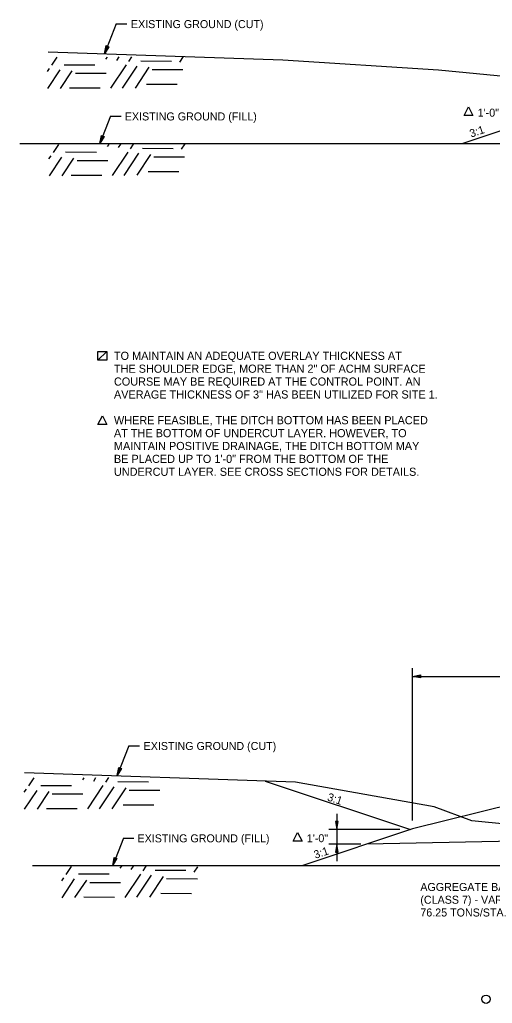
# Model space of a CAD drawing. Extents: x 1398565 to 1398920, y 1968324 to 1968581.
# Drawn here: x 1398564.8 to 1398599.7, y 1968486.6 to 1968559.1 of the extents above; entities that cross this region are included whole.
import ezdxf

# ---------------------------------------------------------------- set-up
doc = ezdxf.new("R2010")
doc.units = 0
for name, color, linetype in [('10', 7, 'Continuous'), ('19', 7, 'Continuous'), ('42', 7, 'Continuous'), ('9', 7, 'Continuous'), ('Default', 7, 'Continuous')]:
    doc.layers.add(name, color=color, linetype=linetype)

msp = doc.modelspace()

# ---------------------------------------------------------------- linework, layer by layer
at = {"layer": '10'}
for points in [[(1398597.924, 1968552.659), (1398598.245, 1968552.018), (1398597.604, 1968552.018)], [(1398570.61, 1968534.616), (1398571.251, 1968534.616), (1398571.251, 1968533.975), (1398570.61, 1968533.975)], [(1398570.61, 1968534.616), (1398571.251, 1968534.616), (1398570.61, 1968533.975)], [(1398570.93, 1968529.866), (1398571.251, 1968529.225), (1398570.61, 1968529.225)], [(1398585.328, 1968499.163), (1398585.649, 1968498.522), (1398585.008, 1968498.522)]]:
    msp.add_lwpolyline(points, close=True, dxfattribs=at)
msp.add_circle((1398599.214, 1968486.865), 0.306, dxfattribs=at)
at = {"layer": '19'}
for p, q in [((1398571.954, 1968558.774), (1398571.097, 1968556.572)), ((1398571.954, 1968558.774), (1398572.736, 1968558.774)), ((1398571.097, 1968556.572), (1398571.217, 1968557.17)), ((1398571.413, 1968557.093), (1398571.097, 1968556.572)), ((1398571.141, 1968556.727), (1398571.268, 1968557.15)), ((1398571.366, 1968557.112), (1398571.169, 1968556.716)), ((1398571.217, 1968557.17), (1398571.413, 1968557.093)), ((1398604.859, 1968552.402), (1398597.492, 1968549.946)), ((1398571.543, 1968551.966), (1398570.757, 1968549.946)), ((1398571.543, 1968551.966), (1398572.325, 1968551.966)), ((1398570.757, 1968549.946), (1398570.877, 1968550.543)), ((1398571.073, 1968550.467), (1398570.757, 1968549.946)), ((1398570.801, 1968550.1), (1398570.928, 1968550.523)), ((1398571.026, 1968550.485), (1398570.829, 1968550.09)), ((1398570.877, 1968550.543), (1398571.073, 1968550.467)), ((1398593.795, 1968500.033), (1398593.795, 1968511.264)), ((1398593.795, 1968510.664), (1398594.395, 1968510.769)), ((1398593.795, 1968510.664), (1398617.795, 1968510.664)), ((1398594.395, 1968510.559), (1398593.795, 1968510.664)), ((1398593.955, 1968510.679), (1398594.395, 1968510.714)), ((1398594.395, 1968510.609), (1398593.955, 1968510.649)), ((1398594.395, 1968510.769), (1398594.395, 1968510.559)), ((1398572.889, 1968505.548), (1398572.033, 1968503.347)), ((1398572.889, 1968505.548), (1398573.672, 1968505.548)), ((1398572.033, 1968503.347), (1398572.153, 1968503.944)), ((1398572.348, 1968503.868), (1398572.033, 1968503.347)), ((1398572.077, 1968503.501), (1398572.204, 1968503.924)), ((1398572.302, 1968503.886), (1398572.105, 1968503.491)), ((1398572.153, 1968503.944), (1398572.348, 1968503.868)), ((1398582.932, 1968502.938), (1398593.647, 1968499.367)), ((1398609.795, 1968503.416), (1398593.795, 1968499.416)), ((1398588.217, 1968500.525), (1398588.217, 1968499.249)), ((1398593.795, 1968499.416), (1398585.707, 1968496.72)), ((1398588.322, 1968499.967), (1398588.112, 1968499.967)), ((1398588.112, 1968499.967), (1398588.217, 1968499.367)), ((1398588.167, 1968499.967), (1398588.202, 1968499.527)), ((1398588.217, 1968499.367), (1398588.322, 1968499.967)), ((1398588.217, 1968499.249), (1398588.217, 1968497.043)), ((1398588.232, 1968499.527), (1398588.272, 1968499.967)), ((1398642.795, 1968499.341), (1398590.426, 1968498.293)), ((1398572.479, 1968498.74), (1398571.693, 1968496.72)), ((1398572.479, 1968498.74), (1398573.261, 1968498.74)), ((1398588.217, 1968498.293), (1398588.112, 1968497.693)), ((1398588.202, 1968498.133), (1398588.167, 1968497.693)), ((1398588.322, 1968497.693), (1398588.217, 1968498.293)), ((1398588.272, 1968497.693), (1398588.232, 1968498.133)), ((1398571.693, 1968496.72), (1398571.812, 1968497.318)), ((1398572.008, 1968497.242), (1398571.693, 1968496.72)), ((1398571.737, 1968496.875), (1398571.864, 1968497.298)), ((1398571.962, 1968497.26), (1398571.765, 1968496.864)), ((1398571.812, 1968497.318), (1398572.008, 1968497.242)), ((1398588.112, 1968497.693), (1398588.322, 1968497.693))]:
    msp.add_line(p, q, dxfattribs=at)
at = {"layer": '42'}
for points in [[(1398613.903, 1968550.586), (1398606.201, 1968553.623), (1398601.314, 1968554.831), (1398595.7, 1968555.373), (1398584.241, 1968556.087), (1398566.939, 1968556.681)], [(1398564.837, 1968549.946), (1398611.333, 1968549.946), (1398635.859, 1968556.055), (1398641.859, 1968556.295)], [(1398564.837, 1968549.946), (1398610.787, 1968549.946)], [(1398612.268, 1968496.72), (1398600.898, 1968499.734), (1398598.177, 1968500.018), (1398595.382, 1968501.049), (1398585.177, 1968502.861), (1398565.203, 1968503.547)], [(1398565.772, 1968496.72), (1398612.268, 1968496.72), (1398636.795, 1968502.83), (1398642.795, 1968503.07)], [(1398565.772, 1968496.72), (1398612.268, 1968496.72), (1398636.795, 1968502.83), (1398642.795, 1968503.07)]]:
    msp.add_lwpolyline(points, dxfattribs=at)
at = {"layer": '9'}
for p, q in [((1398567.214, 1968555.725), (1398567.602, 1968556.308)), ((1398571.198, 1968556.174), (1398571.301, 1968556.328)), ((1398571.995, 1968556.085), (1398572.16, 1968556.333)), ((1398572.886, 1968555.998), (1398573.113, 1968556.338)), ((1398573.775, 1968556.04), (1398576.037, 1968556.034)), ((1398576.65, 1968555.963), (1398576.914, 1968556.36)), ((1398566.876, 1968555.252), (1398567.03, 1968555.483)), ((1398566.904, 1968554.009), (1398567.828, 1968555.394)), ((1398567.857, 1968554.015), (1398568.718, 1968555.307)), ((1398568.104, 1968555.767), (1398570.366, 1968555.761)), ((1398568.941, 1968555.141), (1398571.203, 1968555.135)), ((1398571.555, 1968554.035), (1398572.702, 1968555.756)), ((1398572.415, 1968554.04), (1398573.5, 1968555.667)), ((1398573.367, 1968554.045), (1398574.39, 1968555.58)), ((1398574.613, 1968555.414), (1398576.875, 1968555.408)), ((1398568.502, 1968554.063), (1398570.764, 1968554.057)), ((1398574.174, 1968554.336), (1398576.436, 1968554.33)), ((1398567.336, 1968549.289), (1398567.724, 1968549.872)), ((1398568.226, 1968549.331), (1398570.488, 1968549.325)), ((1398571.32, 1968549.738), (1398571.422, 1968549.892)), ((1398571.677, 1968547.6), (1398572.824, 1968549.32)), ((1398572.117, 1968549.65), (1398572.282, 1968549.897)), ((1398573.008, 1968549.562), (1398573.235, 1968549.903)), ((1398573.897, 1968549.604), (1398576.159, 1968549.598)), ((1398576.772, 1968549.527), (1398577.036, 1968549.924)), ((1398566.998, 1968548.816), (1398567.152, 1968549.047)), ((1398567.026, 1968547.574), (1398567.95, 1968548.959)), ((1398567.979, 1968547.579), (1398568.84, 1968548.871)), ((1398569.063, 1968548.705), (1398571.325, 1968548.699)), ((1398572.537, 1968547.604), (1398573.622, 1968549.232)), ((1398573.489, 1968547.61), (1398574.512, 1968549.144)), ((1398574.735, 1968548.978), (1398576.997, 1968548.972)), ((1398574.296, 1968547.9), (1398576.558, 1968547.894)), ((1398568.624, 1968547.627), (1398570.886, 1968547.621)), ((1398565.513, 1968502.59), (1398565.901, 1968503.173)), ((1398569.497, 1968503.039), (1398569.6, 1968503.193)), ((1398570.294, 1968502.95), (1398570.46, 1968503.198)), ((1398571.185, 1968502.863), (1398571.412, 1968503.203)), ((1398572.075, 1968502.905), (1398574.337, 1968502.899)), ((1398565.175, 1968502.117), (1398565.329, 1968502.348)), ((1398565.203, 1968500.874), (1398566.127, 1968502.259)), ((1398566.156, 1968500.88), (1398567.017, 1968502.172)), ((1398566.403, 1968502.632), (1398568.665, 1968502.626)), ((1398569.854, 1968500.9), (1398571.001, 1968502.621)), ((1398570.714, 1968500.905), (1398571.799, 1968502.532)), ((1398571.666, 1968500.91), (1398572.689, 1968502.445)), ((1398572.912, 1968502.279), (1398575.174, 1968502.273)), ((1398567.241, 1968502.006), (1398569.502, 1968502)), ((1398566.802, 1968500.928), (1398569.064, 1968500.922)), ((1398572.473, 1968501.201), (1398574.735, 1968501.195)), ((1398568.271, 1968496.064), (1398568.66, 1968496.646)), ((1398572.255, 1968496.513), (1398572.358, 1968496.667)), ((1398573.053, 1968496.424), (1398573.218, 1968496.672)), ((1398573.943, 1968496.336), (1398574.17, 1968496.677)), ((1398574.833, 1968496.379), (1398577.095, 1968496.373)), ((1398577.707, 1968496.219), (1398577.971, 1968496.615)), ((1398567.934, 1968495.591), (1398568.087, 1968495.822)), ((1398567.962, 1968494.348), (1398568.885, 1968495.733)), ((1398568.914, 1968494.353), (1398569.776, 1968495.645)), ((1398569.161, 1968496.106), (1398571.423, 1968496.1)), ((1398572.613, 1968494.374), (1398573.759, 1968496.094)), ((1398573.472, 1968494.379), (1398574.557, 1968496.006)), ((1398574.425, 1968494.384), (1398575.448, 1968495.918)), ((1398575.671, 1968495.753), (1398577.933, 1968495.747)), ((1398569.999, 1968495.48), (1398572.261, 1968495.474)), ((1398569.56, 1968494.402), (1398571.822, 1968494.396)), ((1398575.232, 1968494.674), (1398577.494, 1968494.669))]:
    msp.add_line(p, q, dxfattribs=at)
at = {"layer": 'Default'}
for p, q in [((1398592.871, 1968499.367), (1398587.622, 1968499.367)), ((1398589.989, 1968498.293), (1398587.637, 1968498.293))]:
    msp.add_line(p, q, dxfattribs=at)

# ---------------------------------------------------------------- texts
at = {"layer": '10'}
for s, height, rotation, p in [('EXISTING GROUND (CUT)', 0.59001, 360, (1398573.038, 1968558.463)), ('EXISTING GROUND (FILL)', 0.59001, 360, (1398572.585, 1968551.655)), ('1\'-0"', 0.59, 360, (1398598.599, 1968551.932)), ('3:1', 0.59, 18.49392, (1398598.115, 1968550.388)), ('EXISTING GROUND (CUT)', 0.59001, 360, (1398573.973, 1968505.238)), ('3:1', 0.59, 341.52236, (1398587.466, 1968501.529)), ('EXISTING GROUND (FILL)', 0.59001, 360, (1398573.52, 1968498.429)), ('1\'-0"', 0.59, 360, (1398586.002, 1968498.436)), ('3:1', 0.59, 18.49392, (1398586.63, 1968497.213))]:
    msp.add_text(s, height=height, rotation=rotation, dxfattribs=at).set_placement(p)
at = {"layer": '19'}
for s, p in [('AGGREGATE BASE COURSE', (1398594.371, 1968494.842)), ('(CLASS 7) - VAR. COMPACTED DEPTH', (1398594.371, 1968493.902)), ('76.25 TONS/STA.', (1398594.371, 1968492.962))]:
    msp.add_text(s, height=0.59001, rotation=360, dxfattribs=at).set_placement(p)
at = {"layer": '42'}
for s, p in [('TO MAINTAIN AN ADEQUATE OVERLAY THICKNESS AT', (1398571.785, 1968534.002)), ('THE SHOULDER EDGE, MORE THAN 2" OF ACHM SURFACE', (1398571.785, 1968533.052)), ('COURSE MAY BE REQUIRED AT THE CONTROL POINT. AN', (1398571.785, 1968532.102)), ('AVERAGE THICKNESS OF 3" HAS BEEN UTILIZED FOR SITE 1.', (1398571.785, 1968531.152)), ('WHERE FEASIBLE, THE DITCH BOTTOM HAS BEEN PLACED', (1398571.785, 1968529.252)), ('AT THE BOTTOM OF UNDERCUT LAYER. HOWEVER, TO', (1398571.785, 1968528.302)), ('MAINTAIN POSITIVE DRAINAGE, THE DITCH BOTTOM MAY', (1398571.785, 1968527.352)), ('BE PLACED UP TO 1\'-0" FROM THE BOTTOM OF THE', (1398571.785, 1968526.402)), ('UNDERCUT LAYER. SEE CROSS SECTIONS FOR DETAILS.', (1398571.785, 1968525.452))]:
    msp.add_text(s, height=0.6, dxfattribs=at).set_placement(p)

doc.saveas('drawing.dxf')
